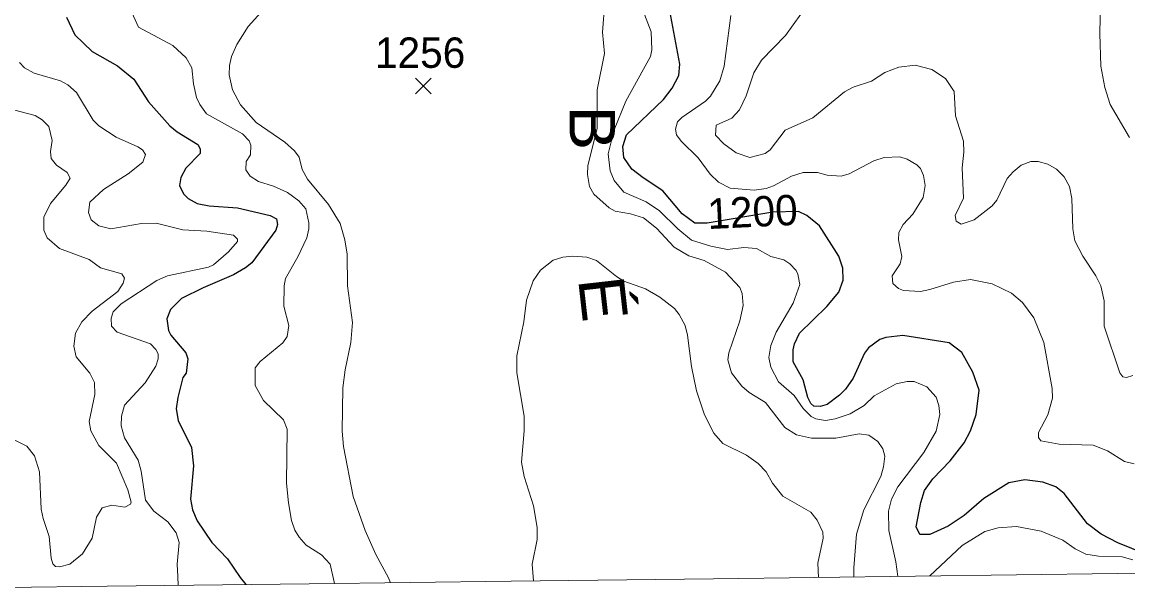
# Model space of a CAD drawing. Extents: x 265 to 291.4, y 7731.5 to 7759.6.
# Drawn here: x 284.274 to 287.186, y 7731.79 to 7733.282 of the extents above; entities that cross this region are included whole.
import ezdxf
from ezdxf.enums import TextEntityAlignment as Align

# ---------------------------------------------------------------- set-up
doc = ezdxf.new("R2010")
doc.units = 0
doc.header["$LTSCALE"] = 0.032
for name, color, linetype, lineweight in [('1', 7, 'Continuous', 25), ('2', 7, 'Continuous', 13), ('21', 7, 'Continuous', 25), ('61', 7, 'Continuous', 13), ('63', 7, 'Continuous', 25)]:
    doc.layers.add(name, color=color, linetype=linetype, lineweight=lineweight)

msp = doc.modelspace()

# ---------------------------------------------------------------- linework, layer by layer
at = {"layer": '1'}
for points in [[(286.5034, 7732.4247), (286.4923, 7732.4111), (286.4628, 7732.3451), (286.4422, 7732.3157), (286.427, 7732.3006), (286.3937, 7732.2759), (286.3754, 7732.2703), (286.3587, 7732.2711), (286.3515, 7732.2783), (286.3435, 7732.2942), (286.3308, 7732.3404), (286.3045, 7732.3881), (286.3045, 7732.4199), (286.3077, 7732.4358), (286.3212, 7732.4637), (286.3936, 7732.5336), (286.4247, 7732.571), (286.4366, 7732.6029), (286.4358, 7732.6347), (286.4247, 7732.6665), (286.3737, 7732.7461), (286.3404, 7732.7731), (286.3184, 7732.7838), (286.251, 7732.7818), (286.0784, 7732.7532), (286.046, 7732.7532), (286.0126, 7732.7779), (285.9617, 7732.8383), (285.9092, 7732.8725), (285.8798, 7732.8956), (285.8583, 7732.9258), (285.8559, 7732.9545), (285.8654, 7732.9855), (285.9633, 7733.0785), (285.9863, 7733.1088), (286.0031, 7733.1414), (286.0062, 7733.1716), (285.9744, 7733.3411)], [(284.3906, 7733.2949), (284.4129, 7733.2488), (284.459, 7733.205), (284.5251, 7733.1668), (284.568, 7733.1318), (284.607, 7733.0722), (284.6627, 7733.0094), (284.6826, 7732.9934), (284.7367, 7732.96), (284.743, 7732.9489), (284.743, 7732.9362), (284.7056, 7732.898), (284.6921, 7732.8733), (284.6889, 7732.8518), (284.6992, 7732.8304), (284.7112, 7732.8176), (284.7351, 7732.8049), (284.7669, 7732.7985), (284.8417, 7732.793), (284.9276, 7732.7731), (284.9443, 7732.7643), (284.9466, 7732.7492), (284.9419, 7732.7349), (284.879, 7732.649), (284.8624, 7732.6355), (284.8305, 7732.6172), (284.751, 7732.5829), (284.6937, 7732.5543), (284.6651, 7732.5257), (284.6555, 7732.501), (284.6595, 7732.4708), (284.6658, 7732.4581), (284.7048, 7732.412), (284.7104, 7732.396), (284.7064, 7732.3586), (284.6969, 7732.3467), (284.6841, 7732.2942), (284.6802, 7732.264), (284.6849, 7732.2338), (284.7199, 7732.1622), (284.7255, 7732.1144), (284.7176, 7732.0269), (284.7231, 7731.9983), (284.735, 7731.9697), (284.774, 7731.9124), (284.8146, 7731.8694), (284.848, 7731.8201), (284.863, 7731.8017)], [(286.7779, 7732.361), (286.7492, 7732.4127), (286.715, 7732.4382), (286.5933, 7732.4573), (286.5488, 7732.4517), (286.5329, 7732.4469), (286.5034, 7732.4247)], [(287.2329, 7731.8821), (287.1597, 7731.9116), (287.116, 7731.9346), (287.0801, 7731.9617), (287.0181, 7732.0412), (286.9966, 7732.0587), (286.9624, 7732.0715), (286.9147, 7732.077), (286.8725, 7732.0691), (286.8065, 7732.0285), (286.7548, 7731.9832), (286.7126, 7731.9553), (286.6649, 7731.9338), (286.6379, 7731.9338), (286.6283, 7731.9538), (286.641, 7732.0174), (286.6506, 7732.0492), (286.672, 7732.0802), (286.7182, 7732.1271), (286.7548, 7732.1749), (286.7715, 7732.2067), (286.7866, 7732.2497), (286.7946, 7732.3133), (286.7779, 7732.361)]]:
    msp.add_lwpolyline(points, dxfattribs=at)
at = {"layer": '2'}
for points in [[(287.1899, 7732.9783), (287.1398, 7733.0658), (287.1255, 7733.1104), (287.1144, 7733.1661), (287.112, 7733.252), (287.1152, 7733.3761), (287.1231, 7733.4318), (287.143, 7733.4763), (287.1748, 7733.5336), (287.1939, 7733.6147)], [(284.9467, 7733.357), (284.8695, 7733.2711), (284.8393, 7733.2233), (284.8258, 7733.1915), (284.8202, 7733.1677), (284.8194, 7733.1438), (284.8281, 7733.104), (284.8496, 7733.0642), (284.8902, 7733.0181), (284.9658, 7732.9664), (284.9912, 7732.9433), (285.0039, 7732.9266), (285.0119, 7732.894), (285.0254, 7732.8686), (285.0811, 7732.8025), (285.1113, 7732.7524), (285.1241, 7732.7095), (285.1304, 7732.6713), (285.1312, 7732.5885), (285.1439, 7732.4915), (285.14, 7732.439), (285.1249, 7732.3674), (285.1185, 7732.3197), (285.1169, 7732.2051), (285.1201, 7732.1654), (285.1455, 7732.0333), (285.1774, 7731.9442), (285.2052, 7731.8806), (285.2391, 7731.8195), (285.2446, 7731.8065)], [(285.0964, 7731.8046), (285.0855, 7731.8551), (285.0622, 7731.8797), (285.0217, 7731.9056), (285.0038, 7731.9262), (284.9925, 7731.9448), (284.9839, 7731.97), (284.9752, 7732.0172), (284.9706, 7732.069), (284.9723, 7732.2105), (284.9623, 7732.2357), (284.9098, 7732.2862), (284.8876, 7732.3261), (284.8882, 7732.3719), (284.9013, 7732.3889), (284.961, 7732.4382), (284.9721, 7732.4549), (284.9761, 7732.4835), (284.9634, 7732.5345), (284.9642, 7732.5885), (284.9681, 7732.6076), (285, 7732.6641), (285.0238, 7732.7142), (285.0294, 7732.7381), (285.0294, 7732.754), (285.0211, 7732.7912), (285.0025, 7732.8118), (284.9733, 7732.8337), (284.9361, 7732.8503), (284.8963, 7732.8629), (284.875, 7732.8769), (284.8631, 7732.8935), (284.8638, 7732.9154), (284.8757, 7732.9327), (284.8764, 7732.9586), (284.8721, 7732.9699), (284.8548, 7732.9885), (284.7599, 7733.041), (284.7419, 7733.0656), (284.7333, 7733.0842), (284.7253, 7733.12), (284.7207, 7733.1619), (284.7064, 7733.1878), (284.6712, 7733.2204), (284.5802, 7733.2689), (284.559, 7733.3173)], [(286.4647, 7731.8218), (286.4646, 7731.8457), (286.4716, 7731.9347), (286.4907, 7731.9983), (286.5352, 7732.0858), (286.5424, 7732.1113), (286.5456, 7732.1399), (286.5408, 7732.159), (286.5273, 7732.1781), (286.5042, 7732.1948), (286.4788, 7732.1987), (286.4167, 7732.1868), (286.3531, 7732.1868), (286.3133, 7732.1956), (286.2823, 7732.2155), (286.2314, 7732.2807), (286.1884, 7732.3077), (286.1693, 7732.3236), (286.1423, 7732.3594), (286.1327, 7732.3929), (286.1351, 7732.412), (286.1645, 7732.4963), (286.1733, 7732.536), (286.1701, 7732.5679), (286.1638, 7732.5838), (286.1264, 7732.6243), (286.0699, 7732.6546), (286.0301, 7732.6673), (285.9911, 7732.6896), (285.945, 7732.7397), (285.9108, 7732.7675), (285.8758, 7732.7779), (285.836, 7732.785), (285.8201, 7732.793), (285.7795, 7732.8296), (285.7684, 7732.8495), (285.7628, 7732.8813), (285.7636, 7732.9052), (285.7883, 7733.0022), (285.7883, 7733.104), (285.8074, 7733.1995), (285.8026, 7733.256), (285.8082, 7733.3347)], [(285.8997, 7733.3363), (285.9307, 7733.2568), (285.9323, 7733.209), (285.9291, 7733.1915), (285.8639, 7733.0738), (285.8328, 7732.999), (285.8177, 7732.9354), (285.8225, 7732.8908), (285.8328, 7732.8654)], [(287.2027, 7732.1192), (287.1772, 7732.1256), (287.1327, 7732.1534), (287.0945, 7732.1685), (287.0054, 7732.1709), (286.9569, 7732.1797), (286.9505, 7732.1892), (286.9505, 7732.2019), (286.9751, 7732.2481), (286.9871, 7732.2926), (286.9863, 7732.3181), (286.9648, 7732.439), (286.9386, 7732.5042), (286.9083, 7732.544), (286.8797, 7732.5686), (286.8288, 7732.5933), (286.7715, 7732.6044), (286.727, 7732.5981), (286.6649, 7732.5782), (286.6395, 7732.5734), (286.5949, 7732.5758), (286.5822, 7732.5814), (286.5671, 7732.5941), (286.5655, 7732.614), (286.5862, 7732.6458), (286.5909, 7732.6649), (286.5822, 7732.7095), (286.583, 7732.7286), (286.5941, 7732.7492), (286.6196, 7732.7763), (286.6466, 7732.8208), (286.6522, 7732.8526), (286.6474, 7732.8781), (286.6395, 7732.8972), (286.6299, 7732.9067), (286.6045, 7732.9218), (286.5854, 7732.9274), (286.544, 7732.9258), (286.517, 7732.9171), (286.4517, 7732.8829), (286.431, 7732.8765), (286.3945, 7732.8797), (286.369, 7732.8861), (286.3308, 7732.8861), (286.2998, 7732.8765), (286.2529, 7732.851), (286.2338, 7732.8439), (286.2019, 7732.8399), (286.1383, 7732.8455), (286.1081, 7732.8606), (286.0858, 7732.8821), (286.0548, 7732.925), (286.0094, 7732.9688), (285.9975, 7732.9855), (285.9943, 7733.0006), (285.9999, 7733.0197), (286.011, 7733.0308), (286.0739, 7733.0746), (286.0866, 7733.0873), (286.1113, 7733.1279), (286.1232, 7733.1661), (286.1407, 7733.2997)], [(286.3244, 7733.3029), (286.2847, 7733.2472), (286.221, 7733.182), (286.2011, 7733.1486), (286.1805, 7733.0881), (286.1637, 7733.0515), (286.1431, 7733.0292), (286.1017, 7733.0109), (286.1001, 7732.9847), (286.1216, 7732.9616), (286.1542, 7732.9378), (286.1908, 7732.9258), (286.2306, 7732.9362), (286.2441, 7732.9465), (286.2831, 7732.9982), (286.3563, 7733.03), (286.4398, 7733.0984), (286.4629, 7733.1112), (286.5106, 7733.1271), (286.5464, 7733.1494), (286.583, 7733.1637), (286.6259, 7733.1692), (286.6697, 7733.1573), (286.7055, 7733.1334), (286.7285, 7733.0992), (286.7325, 7733.0356), (286.7532, 7732.9688), (286.754, 7732.9402)], [(284.2673, 7733.1756), (284.2808, 7733.1621), (284.3055, 7733.1478), (284.3755, 7733.1279), (284.3946, 7733.1175), (284.4177, 7733.0969), (284.4614, 7733.0245), (284.4765, 7733.0093), (284.5219, 7732.9791), (284.5792, 7732.9537), (284.5911, 7732.9457), (284.599, 7732.9338), (284.5919, 7732.9139), (284.5537, 7732.8829), (284.4885, 7732.8415), (284.4527, 7732.8081), (284.4487, 7732.7811), (284.4558, 7732.762), (284.4757, 7732.746), (284.5076, 7732.7381), (284.5887, 7732.7524), (284.6269, 7732.7532), (284.6969, 7732.7357), (284.7605, 7732.7317), (284.8305, 7732.7214), (284.8409, 7732.7111), (284.8409, 7732.7047), (284.8178, 7732.6776), (284.778, 7732.6434), (284.7653, 7732.6371), (284.6571, 7732.6148), (284.6285, 7732.6021), (284.5346, 7732.5408), (284.5139, 7732.5193), (284.5083, 7732.5026), (284.5099, 7732.482), (284.5243, 7732.466), (284.6126, 7732.435), (284.6261, 7732.4207), (284.6324, 7732.4088), (284.6324, 7732.396), (284.6261, 7732.3769), (284.5982, 7732.3324), (284.5441, 7732.2743), (284.5354, 7732.2449), (284.5346, 7732.2194), (284.5441, 7732.1876), (284.5799, 7732.1295), (284.5879, 7732.1001), (284.599, 7732.0238), (284.6213, 7731.9951), (284.6579, 7731.9673), (284.6802, 7731.9378), (284.6873, 7731.9124)], [(284.2124, 7732.2019), (284.2864, 7732.1661), (284.3063, 7732.1407), (284.3198, 7732.0985), (284.3246, 7731.9999), (284.3294, 7731.976), (284.3453, 7731.9283), (284.3508, 7731.871), (284.3548, 7731.8559), (284.362, 7731.8495), (284.3723, 7731.8487), (284.3994, 7731.8551), (284.4328, 7731.8829), (284.459, 7731.9235), (284.4702, 7731.9792), (284.4853, 7732.0039), (284.5107, 7732.011), (284.5442, 7732.0054), (284.5593, 7732.0134), (284.5616, 7732.019), (284.5529, 7732.0508), (284.5227, 7732.1216), (284.4765, 7732.1677), (284.4551, 7732.2067), (284.4511, 7732.2306), (284.4654, 7732.3022), (284.4646, 7732.334), (284.4527, 7732.3579), (284.4161, 7732.4008), (284.4105, 7732.4295), (284.4145, 7732.4637), (284.4312, 7732.4931), (284.4582, 7732.5217), (284.5259, 7732.5734), (284.5402, 7732.5949), (284.5433, 7732.6084), (284.537, 7732.6196), (284.4805, 7732.6355), (284.4511, 7732.657), (284.3723, 7732.6864), (284.3405, 7732.7142), (284.331, 7732.7349), (284.3317, 7732.7691), (284.3485, 7732.8049), (284.389, 7732.8534), (284.4002, 7732.8717), (284.393, 7732.8861), (284.3644, 7732.9059), (284.3508, 7732.9234), (284.3485, 7732.9417), (284.3532, 7732.9704), (284.3445, 7733.0078), (284.327, 7733.0253), (284.3087, 7733.0364), (284.1973, 7733.0658)], [(286.754, 7732.9402), (286.75, 7732.8988), (286.7532, 7732.8192), (286.7309, 7732.7731), (286.7341, 7732.758), (286.7468, 7732.7508), (286.7811, 7732.7619)], [(286.7811, 7732.7619), (286.8288, 7732.7985), (286.8407, 7732.8137), (286.8685, 7732.8709), (286.8837, 7732.8884), (286.9051, 7732.9059), (286.9306, 7732.9155), (286.9497, 7732.9155), (286.9752, 7732.9083), (286.9982, 7732.8948), (287.0181, 7732.8749), (287.0324, 7732.8495), (287.0388, 7732.8176), (287.0412, 7732.7381), (287.0467, 7732.7063), (287.0674, 7732.6665), (287.1016, 7732.6148), (287.1144, 7732.5885), (287.1239, 7732.5488), (287.1239, 7732.482), (287.1645, 7732.3594), (287.1724, 7732.3483), (287.182, 7732.3467), (287.1987, 7732.3523)], [(285.8328, 7732.8654), (285.8591, 7732.8343), (285.9172, 7732.8089), (285.9522, 7732.7858), (286.0007, 7732.7381), (286.0365, 7732.7087), (286.0874, 7732.6927)], [(286.0874, 7732.6927), (286.1319, 7732.684), (286.1749, 7732.6888), (286.2083, 7732.6864), (286.2457, 7732.6657), (286.2799, 7732.6562), (286.2958, 7732.6458), (286.3125, 7732.6283), (286.3173, 7732.6188), (286.3221, 7732.5917), (286.3046, 7732.5424), (286.26, 7732.466), (286.2457, 7732.431), (286.2409, 7732.3992), (286.2457, 7732.3738), (286.2656, 7732.3356), (286.307, 7732.299), (286.3308, 7732.2656), (286.3523, 7732.2441), (286.3642, 7732.2377), (286.3897, 7732.2337), (286.4151, 7732.2377), (286.4549, 7732.2512), (286.4915, 7732.2735), (286.5178, 7732.2982), (286.5758, 7732.33), (286.6045, 7732.3364), (286.6236, 7732.3364), (286.657, 7732.322), (286.6808, 7732.295), (286.688, 7732.2735), (286.6912, 7732.2497), (286.6816, 7732.2059), (286.649, 7732.1494), (286.5798, 7732.0588), (286.5639, 7732.0269), (286.5559, 7731.9951), (286.5567, 7731.9442), (286.575, 7731.8615), (286.5801, 7731.8233)], [(285.6204, 7731.8112), (285.617, 7731.8558), (285.6308, 7731.9203), (285.6308, 7731.9522), (285.6204, 7732.0094), (285.5958, 7732.0858), (285.5894, 7732.124), (285.5958, 7732.2067), (285.5958, 7732.2449), (285.5767, 7732.3594), (285.5767, 7732.404), (285.595, 7732.4931), (285.6021, 7732.5504), (285.6196, 7732.6013), (285.6395, 7732.6291), (285.6722, 7732.6554), (285.6976, 7732.6633), (285.7231, 7732.6665), (285.7612, 7732.6633), (285.7867, 7732.6546), (285.8392, 7732.6124), (285.8583, 7732.6005), (285.9156, 7732.5798), (285.9538, 7732.5583), (285.9919, 7732.5281), (286.0047, 7732.5122), (286.0198, 7732.4835), (286.0261, 7732.4581), (286.0373, 7732.3754), (286.05, 7732.3117), (286.0707, 7732.2481), (286.0954, 7732.2003), (286.1192, 7732.1733), (286.1813, 7732.1423), (286.2123, 7732.12), (286.2338, 7732.0985), (286.2505, 7732.0683), (286.2775, 7732.0341), (286.3507, 7731.9927), (286.3682, 7731.9713), (286.3825, 7731.9394), (286.3833, 7731.9235), (286.3698, 7731.8583), (286.3711, 7731.8207)], [(286.6649, 7731.8243), (286.75, 7731.9044), (286.8089, 7731.9418), (286.8447, 7731.9514), (286.8924, 7731.9545), (286.9577, 7731.9426), (287.0149, 7731.9187), (287.0468, 7731.8957), (287.0754, 7731.8821), (287.1088, 7731.8766), (287.1708, 7731.875), (287.1995, 7731.867)], [(284.6873, 7731.9124), (284.6826, 7731.8551), (284.6842, 7731.8233), (284.6853, 7731.7995)]]:
    msp.add_lwpolyline(points, dxfattribs=at)
at = {"layer": '21'}
for p, q in [((285.3097, 7733.1351), (285.3509, 7733.0939)), ((285.3509, 7733.1351), (285.3097, 7733.0939))]:
    msp.add_line(p, q, dxfattribs=at)
at = {"layer": '63', "lineweight": 13}
msp.add_lwpolyline([(283.9654, 7731.7904), (284.4977, 7731.7971), (285.03, 7731.8038), (285.5623, 7731.8105), (286.0945, 7731.8172), (286.6268, 7731.8239), (287.1591, 7731.8305), (287.6914, 7731.8372), (288.2236, 7731.8438), (288.7559, 7731.8504), (289.2882, 7731.857), (289.8204, 7731.8635), (290.3527, 7731.8701), (290.885, 7731.8766), (291.4172, 7731.8831)], dxfattribs=at)

# ---------------------------------------------------------------- texts
at = {"layer": '61'}
msp.add_text('1256', height=0.08, dxfattribs=at).set_placement((285.3222, 7733.1619), align=Align.CENTER)
at = {"layer": '61', "width": 1.1}
for s, rotation, p in [('B', 270, (285.7158, 7733.0039)), ('É', 276.477, (285.7447, 7732.5475))]:
    msp.add_text(s, height=0.12, rotation=rotation, dxfattribs=at).set_placement(p, align=Align.CENTER)
at = {"layer": '61'}
msp.add_text('1200', height=0.08, rotation=2.742, dxfattribs=at).set_placement((286.1994, 7732.7431), align=Align.CENTER)

doc.saveas('drawing.dxf')
